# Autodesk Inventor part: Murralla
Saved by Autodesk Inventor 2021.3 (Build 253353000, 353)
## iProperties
Created: 2022-09
Part Number: Murralla
Material: Generic
Document SubType Name: Modeling
Designer: Administrator
Density: 1 g/cm^3
Appearance: Default
Title: Murralla v3
Author: Administrator
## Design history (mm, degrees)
feature "Body8"
feature "Socket Body" [Body]
feature "Shade Ring" [Body]
feature "Shade Ring +Collar" [Body]
feature "Socket" [Body]
feature "Body1"
feature "Metal Strain Relief" [Body]
feature "Fabric Cord (1)" [Body]
feature "Stem (Threaded)" [Body]
feature "Cap (Threaded)" [Body]
feature "T9-Bulb" [Body]
body "Solid1"
body "Solid2"
body "Solid3"
body "Solid4"
body "Solid5"
body "Solid6"
body "Solid7"
body "Solid8"
body "Solid9"
body "Solid10"
body "Solid11"
